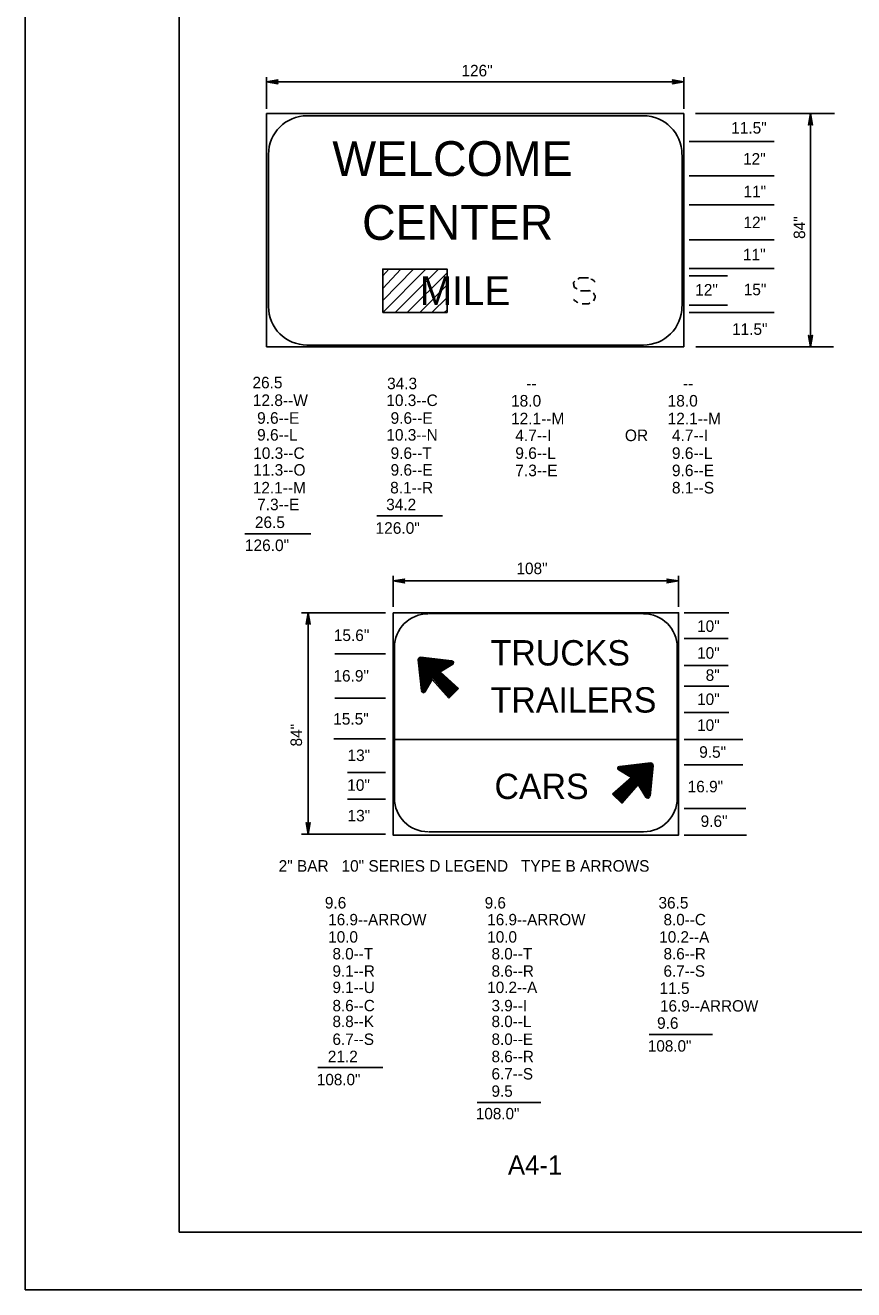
# Model space of a CAD drawing. Extents: x 638689 to 652291, y 298458 to 299646.
# Drawn here: x 651386.3 to 651601.9, y 298457.7 to 298786.8 of the extents above; entities that cross this region are included whole.
import ezdxf

# ---------------------------------------------------------------- set-up
doc = ezdxf.new("R2010")
doc.units = 0
for name, color, linetype in [('1', 7, 'Continuous'), ('2', 7, 'Continuous'), ('3', 7, 'Continuous'), ('PLT-BNDY', 7, 'Continuous')]:
    doc.layers.add(name, color=color, linetype=linetype)

# ---------------------------------------------------------------- blocks, each defined once
blk = doc.blocks.new('RARROW')
at = {"layer": '3'}
blk.add_lwpolyline([(-2.2695, 0.285), (-2.184875, 0.12075), (0, 0), (-2.2695, 0.285), (-2.38575, 0.384625), (0, 0), (-2.183125, -0.108), (-2.262875, -0.2705), (0, 0), (-2.38575, -0.379125), (-2.262875, -0.2705)], dxfattribs=at)

msp = doc.modelspace()

# ---------------------------------------------------------------- linework, layer by layer
at = {"layer": '1'}
for p, q in [((651426.31, 299036.75), (651426.31, 298472.75)), ((652212.31, 298472.75), (651426.31, 298472.75)), ((651426.31, 298472.75), (652012.31, 298472.75))]:
    msp.add_line(p, q, dxfattribs=at)
at = {"layer": '2'}
for p, q in [((651449.06, 298765.12), (651449.06, 298773.37)), ((651449.06, 298772.12), (651557.69, 298772.12)), ((651557.69, 298765.12), (651557.69, 298773.37)), ((651449.06, 298763.87), (651557.69, 298763.87)), ((651449.06, 298703.12), (651449.06, 298763.87)), ((651557.69, 298763.87), (651557.69, 298703.12)), ((651560.69, 298763.87), (651596.84, 298763.87)), ((651590.62, 298703.12), (651590.62, 298763.87)), ((651547.06, 298763.25), (651459.56, 298763.25)), ((651559.06, 298756.62), (651581.16, 298756.62)), ((651449.56, 298753.12), (651449.56, 298713.75)), ((651557.19, 298713.75), (651557.19, 298753.12)), ((651559.06, 298747.62), (651581.16, 298747.62)), ((651559.06, 298740.12), (651581.16, 298740.12)), ((651559.06, 298731), (651581.16, 298731)), ((651559.06, 298723.5), (651581.16, 298723.5)), ((651559.06, 298721.62), (651569.06, 298721.62)), ((651559.06, 298714), (651569.06, 298714)), ((651559.06, 298712.12), (651581.16, 298712.12)), ((651557.69, 298703.12), (651449.06, 298703.12)), ((651459.56, 298703.62), (651547.06, 298703.62)), ((651560.81, 298703.12), (651596.59, 298703.12)), ((651482.02, 298626.09), (651482.02, 298631.59)), ((651480.02, 298623.21), (651466.83, 298623.21)), ((651480.02, 298611.71), (651466.83, 298611.71)), ((651482.02, 298599.59), (651482.02, 298603.21)), ((651480.02, 298601.09), (651466.59, 298601.09)), ((651482.02, 298600.96), (651555.89, 298600.96)), ((651480.02, 298592.34), (651470.14, 298592.34)), ((651480.02, 298585.46), (651470.14, 298585.46)), ((651548.64, 298524.21), (651565.09, 298524.21)), ((651462.43, 298515.59), (651479.3, 298515.59)), ((651503.87, 298506.46), (651520.43, 298506.46))]:
    msp.add_line(p, q, dxfattribs=at)
msp.add_lwpolyline([(651479.31, 298712.12), (651479.31, 298723.37), (651496.06, 298723.37), (651496.06, 298712.12)], close=True, dxfattribs=at)
for points in [[(651479.31, 298712.12), (651490.56, 298723.37)], [(651479.31, 298715.25), (651487.31, 298723.37)], [(651479.31, 298718.37), (651484.06, 298723.37)], [(651479.31, 298721.62), (651480.94, 298723.37)], [(651482.56, 298712.12), (651493.81, 298723.37)], [(651485.69, 298712.12), (651496.06, 298722.37)], [(651488.94, 298712.12), (651496.06, 298719.25)], [(651492.06, 298712.12), (651496.06, 298716)], [(651495.31, 298712.12), (651496.06, 298712.75)], [(651482.02, 298633.96), (651556.27, 298633.96), (651556.27, 298628.84), (651556.27, 298622.21), (651556.27, 298617.21), (651556.27, 298610.59), (651556.27, 298605.46), (651556.27, 298600.59), (651556.27, 298589.59), (651556.27, 298576.09), (651482.02, 298576.09), (651482.02, 298591.59), (651482.02, 298598.34), (651482.02, 298605.46), (651482.02, 298614.09), (651482.02, 298624.84), (651482.02, 298633.96)]]:
    msp.add_lwpolyline(points, dxfattribs=at)
for centre, start, end in [((651459.64, 298753.25), 90, 180), ((651547.12, 298753.25), 0, 90), ((651459.64, 298713.66), 180, 270), ((651547.12, 298713.66), 270, 0)]:
    msp.add_arc(centre, 10.05, start, end, dxfattribs=at)
for points in [[(651532.81, 298721.12), (651532.56, 298721.12), (651532.19, 298721.12), (651530.94, 298721.12), (651530.69, 298721.12), (651530.06, 298720.75)], [(651529.31, 298720.25), (651529.19, 298720.12), (651529.06, 298720), (651529.06, 298719.12), (651529.19, 298718.62), (651529.69, 298718.37), (651529.94, 298718.12)], [(651530.81, 298717.75), (651531.19, 298717.75), (651531.69, 298717.75), (651532.31, 298717.75), (651532.81, 298717.75), (651533.19, 298717.75), (651533.31, 298717.62)], [(651534.56, 298720), (651534.06, 298720.5), (651533.44, 298720.75)], [(651530.06, 298714.62), (651529.94, 298714.75), (651529.56, 298715), (651528.94, 298715.5)], [(651533.06, 298714.37), (651533.19, 298714.5), (651532.81, 298714.37), (651532.19, 298714.37), (651531.56, 298714.37), (651531.19, 298714.37)], [(651534.06, 298717.12), (651534.31, 298716.87), (651534.44, 298716.62), (651534.56, 298716.5), (651534.56, 298716), (651534.44, 298715.62), (651534.19, 298715.12)]]:
    msp.add_spline(points, degree=3, dxfattribs=at)
at = {"layer": '3'}
for p, q in [((651477.75, 298659.14), (651494.84, 298659.14)), ((651443.42, 298654.49), (651460.59, 298654.49)), ((651482.02, 298635.46), (651482.02, 298643.59)), ((651482.02, 298642.21), (651556.27, 298642.21)), ((651556.27, 298635.46), (651556.27, 298643.59)), ((651480.02, 298633.96), (651458.15, 298633.96)), ((651459.9, 298633.96), (651459.9, 298576.34)), ((651557.77, 298633.96), (651569.35, 298633.96)), ((651557.77, 298627.21), (651569.16, 298627.21)), ((651482.39, 298624.84), (651482.39, 298585.59)), ((651497.27, 298621.46), (651489.14, 298622.34)), ((651555.89, 298585.59), (651555.89, 298624.84)), ((651488.52, 298621.71), (651489.39, 298613.71)), ((651488.64, 298622.09), (651488.64, 298622.09)), ((651488.64, 298622.09), (651488.64, 298622.09)), ((651489.14, 298621.84), (651489.14, 298621.84)), ((651494.27, 298618.59), (651497.52, 298620.59)), ((651497.02, 298620.96), (651497.02, 298620.96)), ((651497.89, 298620.96), (651497.89, 298620.96)), ((651497.89, 298620.96), (651497.89, 298620.96)), ((651557.77, 298620.21), (651569.16, 298620.21)), ((651492.14, 298616.59), (651490.39, 298613.46)), ((651492.14, 298616.59), (651492.14, 298616.59)), ((651492.14, 298616.59), (651496.52, 298611.71)), ((651493.27, 298617.59), (651493.27, 298617.59)), ((651494.27, 298618.59), (651494.27, 298618.59)), ((651499.02, 298614.21), (651494.27, 298618.59)), ((651490.02, 298613.71), (651490.02, 298613.71)), ((651490.02, 298612.96), (651490.02, 298612.96)), ((651490.02, 298612.96), (651490.02, 298612.96)), ((651496.52, 298611.71), (651499.02, 298614.21)), ((651499.02, 298614.21), (651499.02, 298614.21)), ((651557.77, 298614.84), (651569.35, 298614.84)), ((651496.52, 298611.71), (651496.52, 298611.71)), ((651557.77, 298607.96), (651569.35, 298607.96)), ((651557.77, 298600.96), (651573.04, 298600.96)), ((651540.39, 298593.34), (651540.39, 298593.34)), ((651540.39, 298593.34), (651540.39, 298593.34)), ((651544.02, 298591.09), (651540.77, 298593.09)), ((651549.02, 298594.84), (651541.02, 298593.96)), ((651541.02, 298593.34), (651541.02, 298593.34)), ((651548.89, 298586.21), (651549.64, 298594.21)), ((651549.02, 298594.21), (651549.02, 298594.21)), ((651557.77, 298594.34), (651573.04, 298594.34)), ((651544.02, 298591.09), (651539.14, 298586.71)), ((651544.02, 298591.09), (651544.02, 298591.09)), ((651544.89, 298590.09), (651544.89, 298590.09)), ((651539.14, 298586.71), (651539.14, 298586.71)), ((651539.14, 298586.71), (651541.52, 298584.34)), ((651541.52, 298584.34), (651545.77, 298589.21)), ((651545.77, 298589.21), (651545.77, 298589.21)), ((651545.77, 298589.21), (651547.77, 298585.96)), ((651548.27, 298586.34), (651548.27, 298586.34)), ((651541.52, 298584.34), (651541.52, 298584.34)), ((651548.27, 298585.59), (651548.27, 298585.59)), ((651548.27, 298585.59), (651548.27, 298585.59)), ((651557.77, 298582.96), (651573.76, 298582.96)), ((651480.02, 298576.34), (651458.15, 298576.34)), ((651557.77, 298576.09), (651574, 298576.09))]:
    msp.add_line(p, q, dxfattribs=at)
for points in [[(651547.14, 298633.71), (651491.27, 298633.71)], [(651488.89, 298621.84), (651489.64, 298613.84), (651489.64, 298613.46), (651490.14, 298613.21), (651490.27, 298613.46), (651492.14, 298617.09), (651492.52, 298616.84), (651496.64, 298612.09), (651498.89, 298614.34), (651494.02, 298618.46), (651494.14, 298618.71), (651497.52, 298620.71), (651497.77, 298620.96), (651497.64, 298621.21), (651497.27, 298621.21), (651489.14, 298622.09), (651488.89, 298622.09), (651488.89, 298621.84), (651489.02, 298621.84), (651490.02, 298613.46), (651492.14, 298617.21), (651496.64, 298612.34), (651498.64, 298614.21), (651493.77, 298618.71), (651497.64, 298620.96), (651489.02, 298621.96), (651490.14, 298613.96), (651492.14, 298617.46), (651496.64, 298612.46), (651498.52, 298614.21), (651493.52, 298618.71), (651497.27, 298620.96), (651489.14, 298621.84), (651490.14, 298614.21), (651492.14, 298617.59), (651496.77, 298612.71), (651498.27, 298614.21), (651493.39, 298618.71), (651496.77, 298620.96), (651489.27, 298621.71), (651490.14, 298614.71), (651492.14, 298617.59), (651496.77, 298612.96), (651498.02, 298614.21), (651493.27, 298618.84), (651496.52, 298620.84), (651489.39, 298621.46), (651490.27, 298615.09), (651492.14, 298617.71), (651496.77, 298613.21), (651497.89, 298614.34), (651493.14, 298618.84), (651496.14, 298620.59), (651489.64, 298621.21), (651490.52, 298615.46), (651492.14, 298617.84), (651496.77, 298613.46), (651497.77, 298614.34), (651493.14, 298618.84), (651495.64, 298620.34), (651489.77, 298621.21), (651490.64, 298616.09), (651492.14, 298618.21), (651496.77, 298613.71), (651497.52, 298614.34), (651493.02, 298618.84), (651495.39, 298620.21), (651490.02, 298620.96), (651490.77, 298616.46), (651492.02, 298618.46), (651496.77, 298613.96), (651497.27, 298614.34), (651492.77, 298618.84), (651494.89, 298620.09), (651490.14, 298620.84), (651490.77, 298616.71), (651492.02, 298618.59), (651496.77, 298614.09), (651497.02, 298614.34), (651492.64, 298618.84), (651494.39, 298620.09), (651490.39, 298620.71), (651490.77, 298617.21), (651492.02, 298618.84), (651496.77, 298614.21), (651496.77, 298614.21), (651492.39, 298618.84), (651494.02, 298619.96), (651490.64, 298620.34), (651490.89, 298617.59), (651492.02, 298618.84), (651496.77, 298614.21), (651492.14, 298618.96), (651493.64, 298619.96), (651490.77, 298620.21), (651491.02, 298617.84), (651492.02, 298618.96), (651494.27, 298616.84), (651492.02, 298619.09), (651493.39, 298619.84), (651490.89, 298620.09)], [(651490.89, 298620.09), (651491.27, 298618.46), (651493.14, 298619.71), (651491.02, 298619.96), (651491.39, 298618.71), (651492.89, 298619.71), (651491.27, 298619.71), (651491.39, 298618.84), (651492.39, 298619.71), (651491.39, 298619.71), (651491.39, 298619.09), (651492.02, 298619.59), (651491.39, 298619.59), (651491.52, 298619.59), (651491.77, 298619.59)], [(651549.02, 298594.59), (651541.14, 298593.71), (651540.77, 298593.71), (651540.64, 298593.34), (651540.77, 298593.21), (651544.27, 298591.09), (651544.27, 298591.09), (651539.39, 298586.71), (651541.64, 298584.46), (651545.64, 298589.21), (651545.89, 298589.21), (651547.89, 298585.96), (651548.27, 298585.71), (651548.39, 298585.96), (651548.52, 298586.21), (651549.39, 298594.34), (651549.39, 298594.46), (651549.14, 298594.71), (651549.02, 298594.34), (651540.77, 298593.46), (651544.52, 298591.09), (651539.52, 298586.71), (651541.52, 298584.46), (651545.89, 298589.71), (651548.27, 298585.96), (651549.27, 298594.46), (651541.14, 298593.34), (651544.64, 298591.09), (651539.77, 298586.71), (651541.52, 298584.96), (651545.89, 298589.84), (651548.14, 298586.34), (651549.02, 298594.21), (651541.52, 298593.34), (651544.77, 298591.09), (651540.02, 298586.71), (651541.52, 298585.21), (651545.89, 298589.96), (651548.14, 298586.59), (651549.02, 298593.96), (651541.89, 298593.21), (651544.89, 298591.21), (651540.39, 298586.71), (651541.52, 298585.46), (651545.89, 298590.09), (651548.02, 298586.84), (651548.89, 298593.96), (651542.39, 298593.21), (651545.27, 298591.21), (651540.64, 298586.71), (651541.64, 298585.59), (651545.89, 298590.34), (651547.77, 298587.34), (651548.52, 298593.71), (651543.02, 298593.09), (651545.39, 298591.21), (651540.77, 298586.71), (651541.64, 298585.71), (651545.89, 298590.34), (651547.77, 298587.71), (651548.39, 298593.59), (651543.39, 298592.84), (651545.52, 298591.21), (651541.02, 298586.71), (651541.64, 298586.09), (651546.02, 298590.46), (651547.77, 298588.09), (651548.27, 298593.46), (651543.64, 298592.71), (651545.64, 298591.21), (651541.14, 298586.71), (651541.64, 298586.34), (651546.02, 298590.71), (651547.64, 298588.59), (651548.02, 298593.34), (651544.14, 298592.71), (651545.77, 298591.21), (651541.27, 298586.71), (651541.64, 298586.34), (651546.02, 298590.96), (651547.39, 298588.96), (651547.89, 298593.21), (651544.52, 298592.71), (651545.89, 298591.21), (651541.52, 298586.71), (651541.52, 298586.46), (651546.14, 298591.09), (651547.27, 298589.46), (651547.77, 298592.84), (651544.89, 298592.59), (651546.02, 298591.34), (651541.52, 298586.59), (651546.39, 298591.21), (651547.27, 298589.84), (651547.77, 298592.71), (651545.39, 298592.46), (651546.39, 298591.34), (651544.27, 298589.21), (651546.52, 298591.34), (651547.14, 298589.96), (651547.64, 298592.59)], [(651547.64, 298592.59), (651545.64, 298592.34), (651547.02, 298590.34), (651547.27, 298592.46), (651545.89, 298592.21), (651547.02, 298590.46), (651547.02, 298592.21), (651546.14, 298592.09), (651546.89, 298591.09), (651546.89, 298592.09), (651546.52, 298591.96), (651546.77, 298591.21), (651546.77, 298591.96), (651546.77, 298591.96), (651546.77, 298591.59)], [(651491.27, 298576.96), (651547.14, 298576.96)]]:
    msp.add_lwpolyline(points, dxfattribs=at)
for centre, radius, start, end in [((651491.12, 298624.93), 8.75, 90, 180), ((651547.19, 298624.93), 8.75, 0, 90), ((651489.08, 298621.78), 0.515, 84.0498, 185.9502), ((651497.16, 298620.94), 0.515, 301.5539, 84.0498), ((651489.92, 298613.69), 0.515, 185.9502, 328.4461), ((651541, 298593.45), 0.515, 95.9502, 238.4461), ((651549.08, 298594.3), 0.515, 354.0498, 95.9502), ((651548.24, 298586.21), 0.515, 211.5539, 354.0498), ((651491.12, 298585.69), 8.75, 180, 270), ((651547.19, 298585.69), 8.75, 270, 0)]:
    msp.add_arc(centre, radius, start, end, dxfattribs=at)
at = {"layer": 'PLT-BNDY'}
msp.add_lwpolyline([(651386.31, 299051.75), (652227.31, 299051.75), (652227.31, 298457.75), (651386.31, 298457.75)], close=True, dxfattribs=at)

# ---------------------------------------------------------------- block references
at = {"layer": '2', "xscale": 1.2574347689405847, "yscale": 1.3092961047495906}
for p, rotation in [((651449.06, 298772.12), 180), ((651590.62, 298763.87), 89.99999999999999), ((651590.62, 298703.12), -90.00000000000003), ((651482.02, 298642.21), 180), ((651459.9, 298633.96), 89.99999999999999), ((651459.9, 298576.34), -90.00000000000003)]:
    msp.add_blockref('RARROW', p, dxfattribs=dict(at, rotation=rotation))
for p in [(651557.69, 298772.12), (651556.27, 298642.21)]:
    msp.add_blockref('RARROW', p, dxfattribs=at)

# ---------------------------------------------------------------- texts
at = {"layer": '2'}
for s, height, p in [('126"', 3, (651499.79, 298773.54)), ('11.5"', 3, (651569.98, 298758.66)), ('WELCOME', 9.049, (651466.19, 298747.62)), ('12"', 3, (651573.06, 298750.57)), ('11"', 3, (651573.19, 298742.09)), ('CENTER', 9.049, (651473.94, 298731)), ('12"', 3, (651573.17, 298734.04)), ('11"', 3, (651573.05, 298725.66)), ('   MILE', 7.54, (651480.56, 298714)), ('12"', 3, (651560.63, 298716.5)), ('15"', 3, (651573.24, 298716.57)), ('11.5"', 3, (651570.2, 298706.26)), ('26.5', 3, (651445.42, 298692.35)), ('34.3', 3, (651480.45, 298692.12)), ('     -- ', 3.016, (651511.07, 298692.1)), ('     -- ', 3.016, (651551.82, 298692.1)), ('12.8--W', 3.016, (651445.5, 298687.74)), ('10.3--C', 3, (651480.25, 298687.74)), ('18.0   ', 3.016, (651512.69, 298687.6)), ('18.0   ', 3.016, (651553.44, 298687.6)), (' 9.6--E', 3.016, (651445.5, 298683.12)), (' 9.6--E', 3, (651480.25, 298683.12)), ('12.1--M', 3.016, (651512.69, 298682.98)), ('12.1--M', 3.016, (651553.44, 298682.98)), (' 9.6--L', 3.016, (651445.5, 298678.74)), ('10.3--N', 3, (651480.25, 298678.74)), (' 4.7--I', 3.016, (651512.69, 298678.6)), ('OR', 3.016, (651542.32, 298678.6)), (' 4.7--I', 3.016, (651553.44, 298678.6)), ('10.3--C', 3, (651445.62, 298673.99)), (' 9.6--T', 3, (651480.25, 298673.99)), (' 9.6--L', 3.016, (651512.69, 298673.98)), (' 9.6--L', 3.016, (651553.44, 298673.98)), ('11.3--O', 3, (651445.62, 298669.62)), (' 9.6--E', 3, (651480.25, 298669.62)), (' 7.3--E', 3.016, (651512.69, 298669.48)), (' 9.6--E', 3.016, (651553.44, 298669.48)), ('12.1--M', 3, (651445.5, 298664.99)), (' 8.1--R', 3.016, (651480.12, 298664.99)), (' 8.1--S', 3.016, (651553.44, 298664.98)), (' 7.3--E', 3.016, (651445.5, 298660.62)), ('34.2', 3, (651480.21, 298660.62)), ('26.5  ', 3, (651446.05, 298655.99)), ('126.0"     ', 3.0158, (651477.44, 298654.49)), ('126.0"', 3.016, (651443.44, 298649.99)), ('A4-1', 5, (651511.89, 298487.7))]:
    msp.add_text(s, height=height, dxfattribs=at).set_placement(p)
msp.add_text('84"', height=3, rotation=90, dxfattribs=at).set_placement((651589.22, 298731.23))
at = {"layer": '3'}
for s, height, p in [('108"', 3, (651514.09, 298643.98)), ('15.6"', 3, (651466.59, 298626.58)), ('10"', 3, (651561.09, 298628.96)), ('TRUCKS', 6.596, (651507.39, 298620.21)), ('10"', 3, (651561.09, 298621.97)), ('16.9"', 3, (651466.49, 298616.02)), ('8"', 3, (651563.34, 298616.21)), ('TRAILERS', 6.596, (651507.39, 298607.96)), ('10"', 3, (651561.09, 298609.93)), ('15.5"', 3, (651466.44, 298604.83)), ('10"', 3, (651561.09, 298603.18)), ('9.5"', 3, (651561.66, 298596.2)), ('13"', 3, (651470.15, 298595.34)), ('10"', 3, (651470.09, 298587.59)), ('CARS', 6.596, (651508.39, 298585.46)), ('16.9"', 3, (651558.65, 298587.2)), ('13"', 3, (651470.16, 298579.64)), ('9.6"', 3, (651562.03, 298578.2)), ('2" BAR   10" SERIES D LEGEND   TYPE B ARROWS', 3, (651452.23, 298566.55)), ('  9.6        ', 3, (651462.02, 298556.96)), ('  9.6        ', 2.9663, (651503.64, 298556.96)), ('36.5     ', 3, (651551.05, 298556.96)), ('16.9--ARROW', 2.9663, (651465.14, 298552.59)), ('16.9--ARROW', 2.9663, (651506.52, 298552.59)), (' 8.0--C    ', 2.9663, (651551.27, 298552.59)), ('10.0       ', 2.9663, (651465.14, 298548.09)), ('10.0       ', 2.9663, (651506.52, 298548.09)), ('10.2--A    ', 2.9663, (651551.27, 298548.09)), (' 8.0--T    ', 2.9663, (651465.14, 298543.71)), (' 8.0--T    ', 2.9663, (651506.52, 298543.71)), (' 8.6--R    ', 2.9663, (651551.27, 298543.71)), (' 9.1--R    ', 2.9663, (651465.14, 298539.21)), (' 8.6--R    ', 2.9663, (651506.52, 298539.21)), (' 6.7--S    ', 2.9663, (651551.27, 298539.21)), (' 9.1--U    ', 2.9663, (651465.14, 298534.96)), ('10.2--A    ', 2.9663, (651506.52, 298534.96)), ('11.5       ', 3, (651551.34, 298534.72)), (' 8.6--C    ', 2.9663, (651465.14, 298530.21)), (' 3.9--I    ', 2.9663, (651506.52, 298530.21)), ('16.9--ARROW', 2.9663, (651551.47, 298530.13)), (' 8.8--K    ', 2.9663, (651465.14, 298526.09)), (' 8.0--L    ', 2.9663, (651506.52, 298526.09)), ('  9.6        ', 3, (651548.46, 298525.65)), (' 6.7--S    ', 2.9663, (651465.14, 298521.46)), (' 8.0--E    ', 2.9663, (651506.52, 298521.46)), ('108.0"       ', 2.9663, (651548.3, 298519.71)), ('21.2       ', 3, (651465.02, 298516.96)), (' 8.6--R    ', 2.9663, (651506.52, 298516.96)), ('108.0"       ', 2.9663, (651462.18, 298510.96)), (' 6.7--S    ', 2.9663, (651506.52, 298512.46)), (' 9.5       ', 2.9663, (651506.52, 298507.96)), ('108.0"        ', 2.9663, (651503.55, 298502.09))]:
    msp.add_text(s, height=height, dxfattribs=at).set_placement(p)
msp.add_text('84"', height=3, rotation=90, dxfattribs=at).set_placement((651458.32, 298599.13))

doc.saveas('drawing.dxf')
